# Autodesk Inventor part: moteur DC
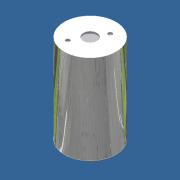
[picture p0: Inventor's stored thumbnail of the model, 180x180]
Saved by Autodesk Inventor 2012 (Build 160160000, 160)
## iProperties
Created: 2011-10
Part Number: moteur DC
Document SubType Name: Modeling
Designer: Laur
Density: 1 g/cm^3
Material: Par défaut
Author: Laur
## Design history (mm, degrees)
sketch "Esquisse1"
  geometry: C1 r 2.5 at (0, 0) reference
extrude "centrage" new body sketch "Esquisse1" distance "d0" = 0.8; taper "d1" = 0 deg
sketch "Esquisse2"
  geometry: C1 r 2.5 at (0, 0) reference; C2 r 6.25 at (0, 0)
  constraints: 1 centre point, 1 coincident
  dimensions: "d2" = 12.5 diameter of C2
extrude "stator" join sketch "Esquisse2" distance "d3" = 21.5; taper "d4" = 0 deg
sketch "Esquisse3"
  geometry: L1 (1.758, 3.076)-(-1.964, -3.436); C1 r 6.25 at (0, 0) reference; C2 r 1.65 at (0, 0); C3 r 0.5 at (1.758, 3.076); C4 r 0.5 at (-1.964, -3.436)
  constraints: 3 centre point, 3 coincident, 2 end point, 1 point on line
  dimensions: "d5" = 3.3 diameter of C2; "d8" = 7.5 distance of L1.start L1.end; "d9" = 1 diameter of C4; "d10" = 1 diameter of C3 (= d9)
extrude "fond moteur" cut sketch "Esquisse3" distance "d6" = 0.5; taper "d7" = 0 deg
sketch "Esquisse4"
  geometry: C1 r 2.5 at (0, 0) reference; C2 r 0.75 at (0, 0)
  constraints: 1 centre point, 1 coincident
  dimensions: "d11" = 1.5 diameter of C2
extrude "alésage arbre" cut sketch "Esquisse4" distance "d12" = 18; taper "d13" = 0 deg
sketch "Esquisse5"
  geometry: C1 r 0.8 at (-2.828, -2.828) reference; C2 r 0.8 at (2.828, 2.828) reference; 2 further points
  constraints: 2 coincident
hole "Perçage1" sketch "Esquisse5" at (2.828, 2.828), (-2.828, -2.828) diameter "d14" = 1.221; stored, may be unused: countersink angle "d18" = 90 deg, drill point angle "d20" = 118 deg; dims "d15" = 6, "d16" = 4, "d17" = 2, "d19" = 2
node "Solide1"
node "Corps solides"
node "Corps surfaciques"
node "Référence1"
node "Référence2"
node "Référence3"
